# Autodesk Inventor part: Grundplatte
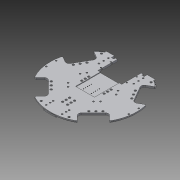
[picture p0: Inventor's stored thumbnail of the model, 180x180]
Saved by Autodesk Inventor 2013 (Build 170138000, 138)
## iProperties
Created: 2012-07
Part Number: Grundplatte
Material: Aluminium 6061
Document SubType Name: Modeling
Designer: rYan
Mass: 173.682 g
Surface Area: 394.861 cm^2
Volume: 64.0895 cm^3
Density: 2.71 g/cm^3
Author: rYan
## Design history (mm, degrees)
sketch "Skizze1"
  geometry: L1 (0, 0)-(-77.076, 44.5); L2 (-129.764, 0)-(129.764, 0) reference; L3 (0, -125)-(0, 127) reference; L4 (0, 0)-(-62.933, -62.933); L5 (0, 0)-(77.076, 44.5); L6 (0, 0)-(77.076, 44.5); L7 (0, 0)-(62.933, -62.933); L8 (-62.958, 62.907)-(-43.926, 51.919); L9 (-43.926, 51.919)-(-66.926, 12.081); L10 (-66.926, 12.081)-(-85.958, 23.07); L11 (-77.058, -44.531)-(-61.518, -28.991); L12 (-61.518, -28.991)-(-28.991, -61.518); L13 (-28.991, -61.518)-(-44.531, -77.058); L14 (62.958, 62.907)-(43.926, 51.919); L15 (43.926, 51.919)-(66.926, 12.081); L16 (66.926, 12.081)-(85.958, 23.07); L17 (77.058, -44.531)-(61.518, -28.991); L18 (61.518, -28.991)-(28.991, -61.518); L19 (28.991, -61.518)-(44.531, -77.058); L20 (-33, 75)-(-33, 72); L21 (33, 72.056)-(33, 75); L22 (-47.917, 75)-(-33, 75); L23 (33, 75)-(47.917, 75); L24 (24, 72)-(24, 32.8); L25 (24, 32.8)-(-24, 32.8); L26 (-24, 32.8)-(-24, 72); L27 (-28, 72)-(-24, 72); L28 (24, 72)-(28, 72); L29 (33, 72.056)-(33, 69); L30 (33, 69)-(28, 69); L31 (28, 69)-(28, 72); L32 (-33, 72)-(-33, 69); L33 (-33, 69)-(-28, 69); L34 (-28, 69)-(-28, 72); C1 r 90 at (0, 1); A1 r 89 centre (0, 0) between (-85.958, 23.07) and (-77.058, -44.531); A2 r 89 centre (0, 0) between (77.058, -44.531) and (85.958, 23.07); A3 r 89 centre (0, 0) between (-44.531, -77.058) and (44.531, -77.058); A4 r 89 centre (0, 0) between (77.058, -44.531) and (85.958, 23.07); A5 r 89 centre (0, 0) between (62.958, 62.907) and (47.917, 75); A6 r 89 centre (0, 0) between (-47.917, 75) and (-62.958, 62.907); A7 r 89 centre (0, 0) between (-85.958, 23.07) and (-77.076, 44.5); 1 further point
  constraints: 64 end point, 16 point on circle, 14 perpendicular, 11 symmetric about line, 8 centre point, 5 parallel, 3 coincident, 1 concentric, 1 midpoint, 1 tangent, 8 other
  dimensions: "d2" = 30 deg angle of L1 L2; "d4" = 45 deg angle of L4 L2; "d6" = 46 distance of L9.end L8.end; "d9" = 46 distance of L11.end L12.end (= d6); "d13" = 178 diameter of A7; "d16" = 66 distance between parallel lines of L21 L20; "d43" = 180 diameter of C1; "d44" = 48 distance of L24.end L25.end; "d130" = 75 distance between parallel lines of L2 L23; "d133" = 5 distance of L32.end L33.end; "d134" = 3 distance of L27.start L33.end; "d135" = 6 distance between parallel lines of L22 L33; "d138" = 64 distance from line of point (0, 0) L9; "d139" = 32.8 distance between parallel lines of L2 L25; "d140" = 64 distance from line of L1.start L12 (derived)
extrude "Extrusion1" new body sketch "Skizze1" distance "d14" = 4; taper "d15" = 0 deg
sketch "Skizze2"
  geometry: L1 (0, -121.8)-(0, 107.8) reference; L2 (-124.6, 0)-(124.6, 0) reference; L3 (22.5, 13)-(22.5, -1); L4 (5, -43)-(5, -57); 2 further points
  constraints: 4 end point, 2 midpoint, 1 parallel, 1 perpendicular
  dimensions: "d99" = 43 distance from line of L4.start L2; "d186" = 5 distance from line of L4.start L1; "d187" = 56 vertical distance of L3.start L4.start; "d188" = 17.5 horizontal distance of L3.start L4.start; "d189" = 7 distance of point (22.5, 6) L3.start; "d190" = 7 distance of L3.end point (22.5, 6) (derived); "d191" = 7 distance of point (5, -50) L4.start (derived); "d192" = 7 distance of L4.end point (5, -50) (derived)
hole "Kickerspule" sketch "Skizze2" at (5, -43), (22.5, 13), (22.5, 6), (22.5, -1), (5, -50), (5, -57) diameter "d21" = 4.2; stored, may be unused: countersink angle "d25" = 90 deg, drill point angle "d27" = 118 deg; dims "d22" = 6, "d23" = 7.5, "d24" = 2, "d26" = 8
sketch "Skizze3"
  geometry: L1 (43.926, 51.919)-(66.926, 12.081) reference; L2 (55.426, 32)-(51.962, 30); L3 (58.712, 18.309)-(48.712, 35.629); L4 (61.518, -28.991)-(28.991, -61.518) reference; L5 (45.255, -45.255)-(42.426, -42.426); L6 (51.972, -32.88)-(37.83, -47.023); L7 (0, 0)-(65.229, 37.66); A1 r 89 centre (0, 0) between (77.058, -44.531) and (85.958, 23.07) reference; 9 further points
  constraints: 10 end point, 6 coincident, 4 midpoint, 4 perpendicular, 2 point on line, 1 collinear
  dimensions: "d29" = 20 distance of L3.start L3.end; "d30" = 4 distance of L5.end L5.start; "d31" = 20 distance of L6.start L6.end; "d76" = 3.5 distance from line of point (53.712, 26.969) L2; "d77" = 3.5 distance from line of point (44.901, -39.952) L5 (= d76); "d180" = 4 distance between parallel lines of L1 L3
hole "Lagerblöcke" sketch "Skizze3" diameter "d32" = 4.2; stored, may be unused: countersink angle "d36" = 90 deg, drill point angle "d38" = 118 deg; dims "d33" = 6, "d34" = 7.5, "d35" = 2, "d37" = 8
sketch "Skizze5"
  geometry: L1 (24, 72)-(28, 72) reference; L2 (24, 32.8)-(24, 72) reference; L3 (26, 61)-(26, 41); L4 (-124.6, 0)-(124.6, 0) reference; 2 further points
  constraints: 2 end point, 1 parallel
  dimensions: "d53" = 20 distance of L3.end L3.start; "d132" = 41 distance from line of L4 L3.end; "d142" = 2 distance between parallel lines of L2 L3
hole "Chipkick" sketch "Skizze5" at (26, 61), (26, 41) diameter "d55" = 2.7; stored, may be unused: countersink angle "d59" = 90 deg, drill point angle "d61" = 118 deg; dims "d56" = 6, "d57" = 5, "d58" = 2.5, "d60" = 8
sketch "Skizze10"
  geometry: L1 (35, 65)-(35, 46); L2 (0, -121.8)-(0, 107.8) reference; L3 (-124.6, 0)-(124.6, 0) reference; 4 further points
  constraints: 2 coincident, 2 end point, 1 midpoint, 1 vertical
  dimensions: "d117" = 19 distance of L1.start L1.end; "d129" = 35 distance from line of L2 L1.end; "d131" = 55.5 distance from line of L3 point (35, 55.5)
hole "Dribbling" sketch "Skizze10" at (35, 55.5), (35, 65), (35, 46) diameter "d121" = 3.2; stored, may be unused: countersink angle "d125" = 90 deg, drill point angle "d127" = 118 deg; dims "d122" = 6, "d123" = 6, "d124" = 2, "d126" = 8
sketch "Skizze6"
  geometry: L1 (0, -121.8)-(0, 107.8) reference; L2 (-124.6, 0)-(124.6, 0) reference; 3 further points
  dimensions: "d65" = 77 distance from line of point (28, -77) L2; "d66" = 28 distance from line of L1 point (28, -77); "d67" = 50 distance from line of L1 point (50, 66); "d68" = 66 distance from line of L2 point (50, 66)
hole "Streben" sketch "Skizze6" at (50, 66), (28, -77) diameter "d69" = 4.2; stored, may be unused: countersink angle "d73" = 90 deg, drill point angle "d75" = 118 deg; dims "d70" = 6, "d71" = 7.5, "d72" = 2, "d74" = 8
sketch "Skizze7"
  geometry: L1 (83, 8)-(83, -12); L2 (-124.6, 0)-(124.6, 0) reference; L3 (0, -121.8)-(0, 107.8) reference; 1 further point
  constraints: 2 end point, 1 vertical
  dimensions: "d78" = 83 distance between parallel lines of L3 L1; "d79" = 20 distance of L1.start L1.end; "d80" = 8 distance from line of L2 L1.start
hole "Gehäusestreben" sketch "Skizze7" at (83, 8), (83, -12) diameter "d81" = 3.2; stored, may be unused: countersink angle "d85" = 90 deg, drill point angle "d87" = 118 deg; dims "d82" = 6, "d83" = 6, "d84" = 2, "d86" = 8
sketch "Skizze9"
  geometry: L1 (58.712, 18.309)-(53.712, 26.969); L2 (38.014, 6.359)-(31.264, 18.05); L3 (58.712, 18.309)-(38.014, 6.359); L4 (51.972, -32.88)-(44.901, -39.952); L5 (51.972, -32.88)-(35.072, -15.981); L6 (35.072, -15.981)-(23.601, -27.452); C1 r 2.1 at (58.712, 18.309) reference; C2 r 2.1 at (53.712, 26.969) reference; C3 r 2.1 at (51.972, -32.88) reference; C4 r 2.1 at (44.901, -39.952) reference; 4 further points
  constraints: 13 end point, 3 perpendicular, 3 point on line, 1 parallel
  dimensions: "d101" = 23.9 distance between parallel lines of L2 L1; "d104" = 3.5 distance from line of L3 point (36.264, 9.39); "d105" = 10 distance of L2.end point (36.264, 9.39); "d113" = 3.5 distance from line of L5 point (32.598, -18.455) (derived); "d114" = 10 distance of point (25.527, -25.527) point (32.598, -18.455); "d115" = 23.9 distance between parallel lines of L4 L6 (derived)
hole "Encoder" sketch "Skizze9" at (31.264, 18.05), (36.264, 9.39), (32.598, -18.455), (25.527, -25.527) diameter "d106" = 3.2; stored, may be unused: countersink angle "d110" = 90 deg, drill point angle "d112" = 118 deg; dims "d107" = 6, "d108" = 6, "d109" = 2, "d111" = 8
sketch "Skizze4"
  geometry: L1 (24, 32.8)-(-24, 32.8) reference; L2 (0, 107.8)-(0, -121.8) reference; L3 (-19, 32.8)-(19, 32.8); L4 (19, 32.8)-(19, -17.2); L5 (19, -17.2)-(-19, -17.2); L6 (-19, -17.2)-(-19, 32.8); 1 further point
  constraints: 8 end point, 2 parallel, 1 horizontal, 1 perpendicular, 1 point on line, 1 other
  dimensions: "d47" = 38 distance of L4.end L5.end; "d49" = 50 distance of L5.end L3.start
extrude "Extrusion2" cut sketch "Skizze4" distance "d50" = 1.5; taper "d51" = 0 deg
sketch "Skizze16"
  geometry: L1 (0, 107.8)-(0, -121.8) reference; L2 (-124.6, 0)-(124.6, 0) reference; 2 further points
  dimensions: "d193" = 8 distance from line of point (-8, -12) L1; "d194" = 12 distance from line of L2 point (-8, -12)
hole "Chip Stopp" sketch "Skizze16" at (-8, -12) diameter "d195" = 1.567; stored, may be unused: countersink angle "d199" = 90 deg, drill point angle "d201" = 118 deg; dims "d196" = 6, "d197" = 4, "d198" = 2, "d200" = 8
pattern_linear "Rechteckige Anordnung1" dims "d204" = 4
node "Spiegelebene"
mirror "Spiegeln1"
fillet "Rundung1" dims "d136" = 0.5
sketch "Skizze11"
  geometry: L1 (16, -62)-(16, -62); L2 (19, -65)-(19, -71); L3 (16, -74)-(16, -74); L4 (13, -71)-(13, -65); L5 (0, -121.8)-(0, 107.8) reference; L6 (-124.6, 0)-(124.6, 0) reference; A1 r 3 centre (16, -65) between (16, -62) and (13, -65); A2 r 3 centre (16, -65) between (19, -65) and (16, -62); A3 r 3 centre (16, -71) between (16, -74) and (19, -71); A4 r 3 centre (16, -71) between (13, -71) and (16, -74); 4 further points
  constraints: 8 end point, 8 point on circle, 8 tangent, 6 point on line, 4 centre point, 2 equal radius, 2 parallel, 1 concentric, 1 horizontal, 1 perpendicular
  dimensions: "d144" = 6 distance of point (13, -62) point (19, -62); "d146" = 12 distance of point (13, -74) point (13, -62); "d147" = 13 distance between parallel lines of L5 L4; "d148" = 62 distance between parallel lines of L6 L1; "d149" = 3 radius of A1
extrude "Extrusion3" cut sketch "Skizze11" distance "d150" = 2; taper "d151" = 0 deg
sketch "Skizze12"
  geometry: A1 r 3 centre (16, -65) between (19, -65) and (13, -65) reference; A2 r 3 centre (16, -71) between (13, -71) and (19, -71) reference; 1 further point
hole "Gummibandhalter" sketch "Skizze12" at (16, -65), (16, -71) diameter "d152" = 3.2; stored, may be unused: countersink angle "d156" = 90 deg, drill point angle "d158" = 118 deg; dims "d153" = 6, "d154" = 4, "d155" = 2, "d157" = 8
mirror "Spiegeln2"
sketch "Skizze13"
  geometry: L1 (0, 123.7)-(0, -124.45) reference; L2 (0, 0)-(-57.618, 85.422); L3 (0, 0)-(54.167, 80.306); L4 (48.65, 72.126)-(49.349, 73.163); L5 (-48.65, 72.126)-(-49.349, 73.163); A1 r 89 centre (0, 0) between (62.958, 62.907) and (47.917, 75) reference; A2 r 88.25 centre (0, 0) between (49.349, 73.163) and (-49.349, 73.163); A3 r 87 centre (0, 0) between (48.65, 72.126) and (-48.65, 72.126); A4 r 89 centre (0, 0) between (77.058, -44.531) and (85.958, 23.07) reference
  constraints: 8 end point, 4 point on circle, 4 point on line, 2 centre point, 2 coincident, 1 other
  dimensions: "d159" = 176.5 diameter of A2; "d161" = 174 diameter of A3; "d164" = 68 deg angle of L2 L3
extrude "Extrusion4" cut sketch "Skizze13" distance "d162" = 2; taper "d163" = 0 deg
fillet "Rundung2" dims "d165" = 0.625
sketch "Skizze14"
  geometry: L1 (-85.285, 22.681)-(-84.164, 22.034) reference; L2 (-85.285, 22.681)-(-85.958, 23.07) reference; L3 (-75.593, -43.066)-(-76.509, -43.982) reference; L4 (-77.058, -44.531)-(-76.509, -43.982) reference; L5 (-43.982, -76.509)-(-43.066, -75.593) reference; L6 (-43.982, -76.509)-(-44.531, -77.058) reference; L7 (43.066, -75.593)-(43.982, -76.509) reference; L8 (44.531, -77.058)-(43.982, -76.509) reference; L9 (76.509, -43.982)-(77.058, -44.531) reference; L10 (76.509, -43.982)-(75.593, -43.066) reference; L11 (84.164, 22.034)-(85.285, 22.681) reference; L12 (85.958, 23.07)-(85.285, 22.681) reference; L13 (0, 0)-(12.386, -88.134); L14 (0, 0)-(-12.386, -88.134); L15 (0, 107.937)-(0, -122.62) reference; L16 (-12.386, -88.134)-(-12.108, -86.153); L17 (12.386, -88.134)-(12.108, -86.153); L18 (-44.531, -77.058)-(-43.066, -75.593); L19 (43.066, -75.593)-(44.531, -77.058); L20 (-12.386, -88.134)-(-12.108, -86.153); A1 r 87 centre (0, 0) between (-84.164, 22.034) and (-75.593, -43.066) reference; A2 r 87 centre (0, 0) between (-43.066, -75.593) and (43.066, -75.593) reference; A3 r 87 centre (0, 0) between (75.593, -43.066) and (84.164, 22.034) reference; A4 r 89 centre (0, 0) between (-85.958, 23.07) and (-77.058, -44.531) reference; A5 r 89 centre (0, 0) between (-44.531, -77.058) and (44.531, -77.058) reference; A6 r 89 centre (0, 0) between (77.058, -44.531) and (85.958, 23.07) reference; A7 r 87 centre (0, 0) between (-43.066, -75.593) and (-12.108, -86.153); A8 r 89 centre (0, 0) between (-44.531, -77.058) and (-12.386, -88.134); A9 r 87 centre (0, 0) between (12.108, -86.153) and (43.066, -75.593); A10 r 89 centre (0, 0) between (12.386, -88.134) and (44.531, -77.058)
  constraints: 14 end point, 13 point on circle, 4 centre point, 4 coincident, 2 collinear, 2 point on line, 1 perpendicular, 1 other
  dimensions: "d207" = 16 deg angle of L13 L14
extrude "Extrusion5" cut sketch "Skizze14" stored distance "d166" = 10; taper "d167" = 0 deg
fillet "Rundung3" dims "d181" = 6
sketch "Skizze18"
  geometry: L1 (16, -71)-(16, -79); C1 r 1.6 at (16, -71) reference; 1 further point
  constraints: 2 end point, 1 vertical
  dimensions: "d208" = 8 distance of L1.end L1.start
hole "Bohrung12" sketch "Skizze18" at (16, -79) diameter "d209" = 3.2; stored, may be unused: countersink angle "d213" = 90 deg, drill point angle "d215" = 118 deg; dims "d210" = 6, "d211" = 6, "d212" = 2, "d214" = 8
sketch "Skizze17"
  geometry: L1 (1.25, -43)-(1.25, -57); L2 (8.75, -57)-(8.75, -43); L3 (18.75, 13)-(18.75, -1); L4 (26.25, -1)-(26.25, 13); A1 r 3.75 centre (5, -43) between (6.346, -46.5) and (3.654, -46.5) reference; A2 r 3.75 centre (5, -57) between (3.654, -53.5) and (6.346, -53.5) reference; A3 r 3.75 centre (5, -43) between (8.75, -43) and (1.25, -43); A4 r 3.75 centre (5, -57) between (1.25, -57) and (8.75, -57); A5 r 3.75 centre (22.5, 13) between (23.846, 9.5) and (21.154, 9.5) reference; A6 r 3.75 centre (22.5, -1) between (21.154, 2.5) and (23.846, 2.5) reference; A7 r 3.75 centre (22.5, 13) between (26.25, 13) and (18.75, 13); A8 r 3.75 centre (22.5, -1) between (18.75, -1) and (26.25, -1); 1 further point
  constraints: 17 point on circle, 8 end point, 6 tangent, 4 centre point, 4 coincident
extrude "Extrusion6" cut sketch "Skizze17" distance "d205" = 2; taper "d206" = 0 deg
chamfer "Fase2" distance "d182" = 1.5; stored, may be unused: second distance "d183" = 2, angle "d184" = 45 deg
fillet "Rundung4" dims "d185" = 2
mirror "Spiegeln3"
node "Volumenkörper1"
other parameters: "d0" = 175, "d10" = 175
